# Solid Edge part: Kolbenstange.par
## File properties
Username: bmolnar
Dokumentum tartalom típus: 0
Author: bmolnar
Last saved by: bmolnar
Revision: 79
Sűrűség: 0,000 kg/m^3
Pontosság: 0,990
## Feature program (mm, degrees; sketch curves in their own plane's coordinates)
base feature "unnamed BaseFeature 1"
sketch for "unnamed Protrusion 1" plane through (23.3, 0, 0) normal (1, 0, 0) x-axis (0, -1, 0)
  circle centre (0, 0) radius 10
extrude "unnamed Protrusion 1" add finite 6.7 along +normal
sketch for "Furat_1" plane through (-5, 0, 0) normal (-1, 0, 0) x-axis (0, 1, 0)
hole "Furat_1" diameter 6 finite  VBottomAngle = 118 deg; ThreadDepth = 15 mm
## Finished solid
Body 1: solid body, 14 faces, 20 edges, 8 vertices.
  Faces by surface: plane 7, cylinder 4, cone 2, torus 1
  Edges by curve: circle 10, line 6, ellipse 2, intersection 2
Bounding box of the edges (mm; curved faces can reach further): 35.000 x 20.000 x 20.000, from (-5, -10, -10) to (30, 10, 10).
Cylindrical faces by radius (mm): R2.4585 x2, R5 x1, R10 x1
Conical faces (half-angle, radius in mm at the cone's reference point): 45 deg R2.8085 x1, 59 deg R2.4585 x1
Toroidal faces (ring radius, tube radius in mm): R3.8 r1.2 x1
Planar faces by outward normal: +x 1, +z 1, -x 2, -z 1, oblique 2
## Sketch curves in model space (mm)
circle centre (23.3, 0, 0) radius 10
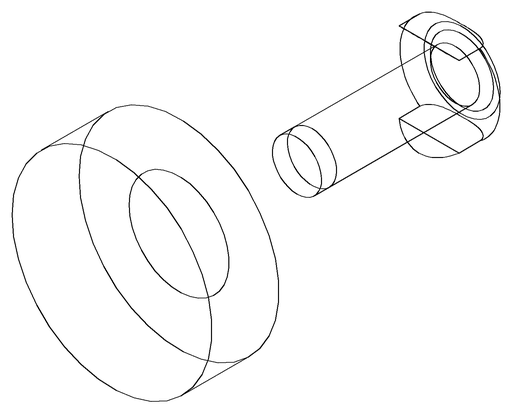
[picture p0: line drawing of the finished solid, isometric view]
